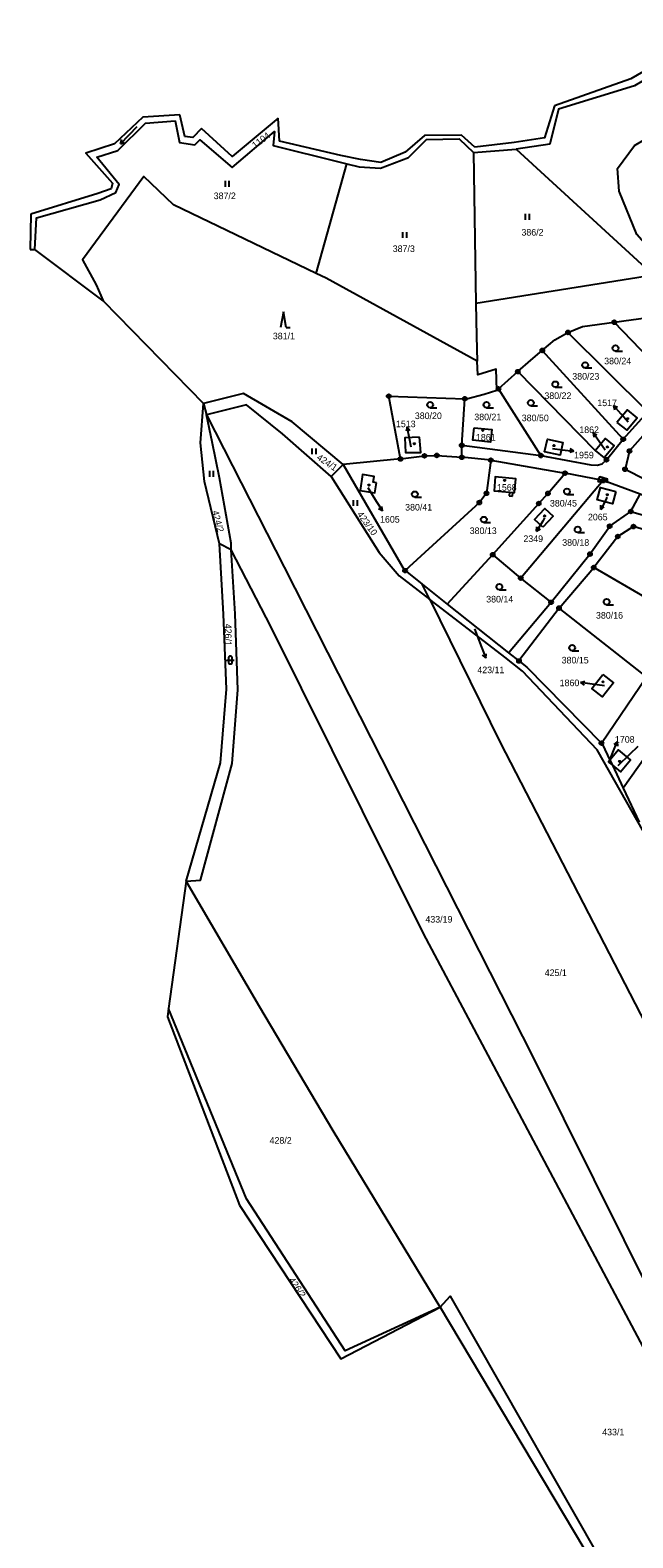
# Model space of a CAD drawing. Extents: x -680203 to -673936, y -1102717 to -1093650.
# Drawn here: x -680070.7 to -679915.5, y -1098200.7 to -1097812.6 of the extents above; entities that cross this region are included whole.
import ezdxf

# ---------------------------------------------------------------- set-up
doc = ezdxf.new("R2010")
doc.units = 0
for name, color, linetype in [('SOxx02xx_Koleje_param další_Popis10', 7, 'Continuous'), ('SOxx02xx_Staničení_Popis10', 7, 'Continuous'), ('SOxxxxxx_Koleje_hlavní_body_Popis10', 7, 'Continuous'), ('SOxxxxxx_Koleje_LN_parametry_Popis10', 7, 'Continuous'), ('SOxxxxxx_Koleje_param další_Popis10', 7, 'Continuous'), ('SOxxxxxx_Osa_bod_P', 7, 'Continuous'), ('SOxxxxxx_Staničení_Popis10', 7, 'Continuous'), ('x_prac', 7, 'Continuous')]:
    doc.layers.add(name, color=color, linetype=linetype)

msp = doc.modelspace()

# ---------------------------------------------------------------- linework, layer by layer
at = {"layer": 'SOxx02xx_Koleje_param další_Popis10'}
for centre, radius in [((-679932.24, -1097890.38), 0.5), ((-679932.24, -1097890.38), 0.0303), ((-679920.32, -1097887.77), 0.5), ((-679920.32, -1097887.77), 0.0303), ((-679938.84, -1097895.02), 0.5), ((-679938.84, -1097895.02), 0.0303), ((-679945.15, -1097900.49), 0.5), ((-679945.15, -1097900.49), 0.0303), ((-679978.36, -1097906.79), 0.5), ((-679950.11, -1097904.92), 0.5), ((-679950.11, -1097904.92), 0.0303), ((-679978.36, -1097906.79), 0.0303), ((-679958.78, -1097907.47), 0.5), ((-679958.78, -1097907.47), 0.0303), ((-679918.02, -1097917.9), 0.5), ((-679918.02, -1097917.9), 0.0303), ((-679969.15, -1097922.15), 0.5), ((-679965.98, -1097922.05), 0.5), ((-679959.58, -1097919.45), 0.5), ((-679959.58, -1097919.45), 0.0303), ((-679939.21, -1097922.09), 0.5), ((-679916.41, -1097920.91), 0.5), ((-679916.41, -1097920.91), 0.0303), ((-679975.33, -1097922.97), 0.5), ((-679975.33, -1097922.97), 0.0303), ((-679969.15, -1097922.15), 0.0303), ((-679965.98, -1097922.05), 0.0303), ((-679959.57, -1097922.54), 0.5), ((-679959.57, -1097922.54), 0.0303), ((-679952.08, -1097923.27), 0.5), ((-679952.08, -1097923.27), 0.0303), ((-679939.21, -1097922.09), 0.0303), ((-679922.32, -1097923.17), 0.5), ((-679922.32, -1097923.17), 0.0303), ((-679917.56, -1097925.62), 0.5), ((-679917.56, -1097925.62), 0.0303), ((-679933, -1097926.62), 0.5), ((-679933, -1097926.62), 0.0303), ((-679923.14, -1097928.54), 0.5), ((-679923.14, -1097928.54), 0.0303), ((-679953.2, -1097931.81), 0.5), ((-679953.2, -1097931.81), 0.0303), ((-679937.39, -1097931.84), 0.5), ((-679937.39, -1097931.84), 0.0303), ((-679955.05, -1097934.19), 0.5), ((-679955.05, -1097934.19), 0.0303), ((-679939.73, -1097934.44), 0.5), ((-679939.73, -1097934.44), 0.0303), ((-679916.06, -1097936.49), 0.5), ((-679916.06, -1097936.49), 0.0303), ((-679921.5, -1097940.27), 0.5), ((-679921.5, -1097940.27), 0.0303), ((-679915.37, -1097940.37), 0.5), ((-679919.41, -1097942.93), 0.5), ((-679919.41, -1097942.93), 0.0303), ((-679951.59, -1097947.6), 0.5), ((-679951.59, -1097947.6), 0.0303), ((-679926.57, -1097947.45), 0.5), ((-679926.57, -1097947.45), 0.0303), ((-679974.15, -1097951.71), 0.5), ((-679974.15, -1097951.71), 0.0303), ((-679925.61, -1097950.92), 0.5), ((-679925.61, -1097950.92), 0.0303), ((-679944.39, -1097953.65), 0.5), ((-679944.39, -1097953.65), 0.0303), ((-679936.59, -1097959.86), 0.5), ((-679936.59, -1097959.86), 0.0303), ((-679934.54, -1097961.35), 0.5), ((-679934.54, -1097961.35), 0.0303), ((-679944.85, -1097974.97), 0.5), ((-679944.85, -1097974.97), 0.0303), ((-679923.62, -1097996.14), 0.5), ((-679923.62, -1097996.14), 0.0303)]:
    msp.add_circle(centre, radius, dxfattribs=at)
at = {"layer": 'SOxx02xx_Staničení_Popis10'}
for p, q in [((-679918.56, -1097911.46), (-679920.53, -1097909.2)), ((-679920.53, -1097909.2), (-679919.49, -1097909.62)), ((-679920.53, -1097909.2), (-679920.25, -1097910.28)), ((-679916.78, -1097913.51), (-679918.56, -1097911.46)), ((-679973.61, -1097914.74), (-679973.91, -1097915.82)), ((-679973.04, -1097917.69), (-679973.61, -1097914.74)), ((-679973.61, -1097914.74), (-679972.93, -1097915.63)), ((-679972.61, -1097919.91), (-679973.04, -1097917.69)), ((-679924.06, -1097918.71), (-679925.78, -1097916.25)), ((-679925.78, -1097916.25), (-679924.8, -1097916.78)), ((-679925.78, -1097916.25), (-679925.62, -1097917.36)), ((-679936.2, -1097920.29), (-679933.69, -1097920.58)), ((-679933.69, -1097920.58), (-679930.71, -1097920.95)), ((-679930.71, -1097920.95), (-679931.77, -1097921.32)), ((-679930.71, -1097920.95), (-679931.64, -1097920.33)), ((-679922.68, -1097920.7), (-679924.06, -1097918.71)), ((-679983.72, -1097930.34), (-679981.6, -1097933.8)), ((-679922.45, -1097933.3), (-679923.81, -1097935.97)), ((-679922.2, -1097932.81), (-679922.45, -1097933.3)), ((-679981.6, -1097933.8), (-679980.01, -1097936.34)), ((-679980.01, -1097936.34), (-679980.96, -1097935.76)), ((-679980.01, -1097936.34), (-679980.12, -1097935.23)), ((-679923.81, -1097935.97), (-679923.8, -1097934.85)), ((-679923.81, -1097935.97), (-679922.91, -1097935.31)), ((-679938.75, -1097939), (-679940.3, -1097941.57)), ((-679940.3, -1097941.57), (-679940.21, -1097940.46)), ((-679940.3, -1097941.57), (-679939.35, -1097940.97)), ((-679938.25, -1097938.16), (-679938.75, -1097939)), ((-679956.32, -1097966.73), (-679954.48, -1097971.42)), ((-679954.48, -1097971.42), (-679953.41, -1097974.22)), ((-679953.41, -1097974.22), (-679954.23, -1097973.47)), ((-679953.41, -1097974.22), (-679953.3, -1097973.11)), ((-679928.99, -1097980.55), (-679927.93, -1097980.2)), ((-679926.02, -1097980.97), (-679928.99, -1097980.55)), ((-679928.99, -1097980.55), (-679928.07, -1097981.19)), ((-679922.85, -1097981.41), (-679926.02, -1097980.97)), ((-679921.62, -1098000.91), (-679920.68, -1097998.54)), ((-679920.68, -1097998.54), (-679919.56, -1097995.76)), ((-679919.56, -1097995.76), (-679920.4, -1097996.5)), ((-679919.56, -1097995.76), (-679919.47, -1097996.87)), ((-679919.28, -1098001.87), (-679916.3, -1097998.95)), ((-679916.3, -1097998.95), (-679914.14, -1097996.86))]:
    msp.add_line(p, q, dxfattribs=at)
at = {"layer": 'SOxxxxxx_Koleje_hlavní_body_Popis10'}
for p, q in [((-680043.2, -1097837.5), (-680047.37, -1097841.81)), ((-680047.37, -1097841.81), (-680047.05, -1097840.76)), ((-680047.37, -1097841.81), (-680046.33, -1097841.46)), ((-680020.4, -1097852.9), (-680020.4, -1097851.4)), ((-680019.4, -1097852.9), (-680019.4, -1097851.4)), ((-679943.15, -1097861.39), (-679943.15, -1097859.89)), ((-679942.15, -1097861.39), (-679942.15, -1097859.89)), ((-679974.75, -1097866.06), (-679974.75, -1097864.56)), ((-679973.75, -1097866.06), (-679973.75, -1097864.56)), ((-680005.49, -1097885.12), (-680006.24, -1097889.12)), ((-680004.74, -1097889.12), (-680005.49, -1097885.12)), ((-680004.74, -1097889.12), (-680003.74, -1097889.12)), ((-679919.99, -1097895.2), (-679918.24, -1097895.2)), ((-679927.82, -1097899.54), (-679926.07, -1097899.54)), ((-679935.5, -1097904.48), (-679933.75, -1097904.48)), ((-679967.72, -1097909.78), (-679965.97, -1097909.78)), ((-679953.19, -1097909.78), (-679951.44, -1097909.78)), ((-679941.81, -1097909.28), (-679940.06, -1097909.28)), ((-679998.06, -1097921.76), (-679998.06, -1097920.26)), ((-679997.06, -1097921.76), (-679997.06, -1097920.26)), ((-680024.44, -1097927.55), (-680024.44, -1097926.05)), ((-680023.44, -1097927.55), (-680023.44, -1097926.05)), ((-679987.43, -1097935.04), (-679987.43, -1097933.54)), ((-679986.43, -1097935.04), (-679986.43, -1097933.54)), ((-679971.65, -1097932.81), (-679969.9, -1097932.81)), ((-679932.5, -1097932.07), (-679930.75, -1097932.07)), ((-679953.9, -1097939.33), (-679952.15, -1097939.33)), ((-679929.74, -1097941.89), (-679927.99, -1097941.89)), ((-679949.9, -1097956.63), (-679948.15, -1097956.63)), ((-679922.28, -1097960.5), (-679920.53, -1097960.5)), ((-679931.15, -1097972.34), (-679929.4, -1097972.34)), ((-680020.13, -1097974.73), (-680018.13, -1097974.73)), ((-680019.63, -1097974.23), (-680019.63, -1097975.23)), ((-680018.63, -1097975.23), (-680018.63, -1097974.23))]:
    msp.add_line(p, q, dxfattribs=at)
for centre in [(-679919.99, -1097894.45), (-679927.82, -1097898.79), (-679935.5, -1097903.73), (-679967.72, -1097909.03), (-679953.19, -1097909.03), (-679941.81, -1097908.53), (-679971.65, -1097932.06), (-679932.5, -1097931.32), (-679953.9, -1097938.58), (-679929.74, -1097941.14), (-679949.9, -1097955.88), (-679922.28, -1097959.75), (-679931.15, -1097971.59)]:
    msp.add_circle(centre, 0.75, dxfattribs=at)
for centre, start, end in [((-680019.13, -1097974.23), 0, 180), ((-680019.13, -1097975.23), 180, 359.9879)]:
    msp.add_arc(centre, 0.5, start, end, dxfattribs=at)
at = {"layer": 'SOxxxxxx_Koleje_LN_parametry_Popis10'}
for points in [[(-679924.53, -1097928.79), (-679923.95, -1097928.88), (-679923.79, -1097928.41), (-679924.45, -1097928.29)], [(-679924.45, -1097928.29), (-679923.79, -1097928.41), (-679923.74, -1097928.27), (-679922.67, -1097928.57), (-679922.68, -1097928.71), (-679922.08, -1097928.93), (-679922.07, -1097928.13), (-679924.06, -1097927.55)]]:
    msp.add_lwpolyline(points, close=True, dxfattribs=at)
at = {"layer": 'SOxxxxxx_Koleje_param další_Popis10'}
for centre in [(-679916.86, -1097912.62), (-679954.15, -1097915.61), (-679971.78, -1097919.05), (-679935.84, -1097919.52), (-679922.1, -1097919.85), (-679983.47, -1097929.7), (-679948.53, -1097928.5), (-679922.13, -1097932.17), (-679938.26, -1097937.63), (-679923.22, -1097980.34), (-679921.35, -1098001.12), (-679918.95, -1098000.82)]:
    msp.add_circle(centre, 0.175, dxfattribs=at)
at = {"layer": 'SOxxxxxx_Staničení_Popis10'}
msp.add_line((-679947.26, -1097931.51), (-679946.44, -1097931.59), dxfattribs=at)
at = {"layer": 'x_prac'}
for p, q in [((-680032.12, -1097834.34), (-680041.62, -1097834.93)), ((-680006.46, -1097841.12), (-680006.86, -1097835.19)), ((-679959.68, -1097839.57), (-679969.2, -1097839.65)), ((-679956.25, -1097842.69), (-679959.68, -1097839.57)), ((-679956.59, -1097844.07), (-679945.55, -1097843.21)), ((-679956.59, -1097844.07), (-679955.91, -1097882.92)), ((-679945.55, -1097843.21), (-679910.23, -1097875.63)), ((-679997.01, -1097875.2), (-679989.15, -1097846.99)), ((-680053.24, -1097854.63), (-680070.47, -1097859.92)), ((-680070.47, -1097859.92), (-680070.65, -1097869)), ((-680070.65, -1097869), (-680069.42, -1097869.02)), ((-680051.84, -1097882.27), (-680069.42, -1097869.02)), ((-679994.49, -1097876.41), (-679997.01, -1097875.2)), ((-680053.69, -1097878.16), (-680051.84, -1097882.27)), ((-679955.65, -1097897.8), (-679994.49, -1097876.41)), ((-679910.23, -1097875.63), (-679955.91, -1097882.92)), ((-680051.84, -1097882.27), (-680026, -1097908.7)), ((-679955.91, -1097882.92), (-679955.76, -1097891.32)), ((-679911.68, -1097910.84), (-679932.24, -1097890.38)), ((-679905.14, -1097903.62), (-679920.32, -1097887.77)), ((-679955.76, -1097891.32), (-679955.65, -1097897.8)), ((-679918.02, -1097917.9), (-679938.84, -1097895.02)), ((-679950.11, -1097904.92), (-679945.15, -1097900.49)), ((-679945.15, -1097900.49), (-679925.2, -1097920.79)), ((-679950.51, -1097905.28), (-679950.11, -1097904.92)), ((-679939.21, -1097922.09), (-679950.11, -1097904.92)), ((-680026, -1097908.7), (-680025.27, -1097911.61)), ((-679959.58, -1097919.45), (-679958.78, -1097907.47)), ((-679918.02, -1097917.9), (-679911.68, -1097910.84)), ((-679922.32, -1097923.17), (-679918.02, -1097917.9)), ((-679959.57, -1097922.54), (-679959.58, -1097919.45)), ((-679959.58, -1097919.45), (-679939.21, -1097922.09)), ((-679925.2, -1097920.79), (-679922.89, -1097922.65)), ((-679993.21, -1097927.47), (-679990.1, -1097924.39)), ((-679975.33, -1097922.97), (-679990.1, -1097924.39)), ((-679952.08, -1097923.27), (-679959.57, -1097922.54)), ((-679952.08, -1097923.27), (-679933, -1097926.62)), ((-679922.89, -1097922.65), (-679922.32, -1097923.17)), ((-680021.96, -1097944.82), (-680025.77, -1097928.73)), ((-679923.14, -1097928.54), (-679944.39, -1097953.65)), ((-679923.14, -1097928.54), (-679933, -1097926.62)), ((-679913.64, -1097932.02), (-679923.14, -1097928.54)), ((-679947.34, -1097932.44), (-679946.52, -1097932.51)), ((-679916.06, -1097936.49), (-679913.64, -1097932.02)), ((-680020.91, -1097962.93), (-680021.96, -1097944.82)), ((-680018.89, -1097946.34), (-680021.96, -1097944.82)), ((-680018.89, -1097946.34), (-680018.96, -1097944.64)), ((-680017.91, -1097962.81), (-680018.89, -1097946.34)), ((-679963.31, -1097960.31), (-679951.59, -1097947.6)), ((-679944.39, -1097953.65), (-679951.59, -1097947.6)), ((-679974.15, -1097951.71), (-679969.77, -1097955.18)), ((-679934.54, -1097961.35), (-679925.61, -1097950.92)), ((-679901.33, -1097965.01), (-679925.61, -1097950.92)), ((-679975.64, -1097953.08), (-679967.83, -1097959.12)), ((-679969.77, -1097955.18), (-679963.31, -1097960.31)), ((-679967.83, -1097959.12), (-679969.77, -1097955.18)), ((-679936.59, -1097959.86), (-679944.39, -1097953.65)), ((-679963.31, -1097960.31), (-679947.52, -1097972.84)), ((-679947.52, -1097972.84), (-679936.59, -1097959.86)), ((-679934.54, -1097961.35), (-679944.85, -1097974.97)), ((-679912.02, -1097979.05), (-679934.54, -1097961.35)), ((-679947.52, -1097972.84), (-679944.85, -1097974.97)), ((-679923.62, -1097996.14), (-679912.02, -1097979.05)), ((-679901.27, -1097983.98), (-679918.05, -1098007.7)), ((-680030.49, -1098031.65), (-680021.65, -1098001.16)), ((-679921.43, -1098000.47), (-679920.8, -1098001.82)), ((-679920.8, -1098001.82), (-679918.05, -1098007.7)), ((-679918.05, -1098007.7), (-679913.92, -1098016.51)), ((-680030.49, -1098031.65), (-680035.04, -1098064.4)), ((-680035.04, -1098064.4), (-680035.34, -1098066.58)), ((-680014.99, -1098113.45), (-680035.04, -1098064.4))]:
    msp.add_line(p, q, dxfattribs=at)
for points in [[(-679894.47, -1097812.57), (-679916.06, -1097825.13), (-679935.71, -1097832.08)], [(-679905.81, -1097821.39), (-679915.09, -1097826.89), (-679934.68, -1097832.95), (-679936.92, -1097841.89), (-679945.55, -1097843.21)], [(-679905.39, -1097874.69), (-679910.72, -1097869.5), (-679914.54, -1097865.19), (-679919.02, -1097854.02), (-679919.51, -1097848.2), (-679915.14, -1097842.24), (-679910.49, -1097839.56), (-679899.01, -1097837.6), (-679890.96, -1097834.49), (-679881.95, -1097827.47), (-679874.33, -1097827.56), (-679868.96, -1097846.47), (-679865.52, -1097860.62)], [(-679935.71, -1097832.08), (-679938.26, -1097840.26), (-679946.05, -1097841.52), (-679956.25, -1097842.69)], [(-680069.42, -1097869.02), (-680068.99, -1097860.87), (-680052.65, -1097856.27), (-680048.64, -1097854.4), (-680047.76, -1097852.3), (-680053.5, -1097845.3), (-680048.09, -1097843.52), (-680040.97, -1097836.52), (-680033.32, -1097835.94), (-680032.18, -1097841.48), (-680028.27, -1097842.06), (-680026.99, -1097840.82), (-680018.66, -1097847.9), (-680007.73, -1097838.63), (-680008.08, -1097842.26), (-679991.22, -1097846.5), (-679989.15, -1097846.99)], [(-680041.62, -1097834.93), (-680048.92, -1097841.87), (-680056.31, -1097844.27), (-680049.48, -1097851.98), (-680049.8, -1097853.43), (-680053.24, -1097854.63)], [(-680026.58, -1097837.92), (-680028.82, -1097840.21), (-680030.84, -1097839.99), (-680032.12, -1097834.34)], [(-680006.86, -1097835.19), (-680018.67, -1097845.08), (-680026.58, -1097837.92)], [(-679969.2, -1097839.65), (-679974.14, -1097844.02), (-679980.36, -1097846.62)], [(-679980.36, -1097846.62), (-679985.6, -1097845.9), (-679990.67, -1097844.88), (-680006.46, -1097841.12)], [(-679989.15, -1097846.99), (-679985.98, -1097847.74), (-679980.46, -1097848.12), (-679973.32, -1097845.32), (-679968.61, -1097840.73), (-679960.2, -1097840.52), (-679956.59, -1097844.07)], [(-679997.01, -1097875.2), (-680033.8, -1097857.51), (-680041.36, -1097850.22), (-680057.22, -1097871.74), (-680053.69, -1097878.16)], [(-679920.32, -1097887.77), (-679904.73, -1097885.63), (-679892.06, -1097885.34)], [(-679938.84, -1097895.02), (-679935.63, -1097892.33), (-679932.24, -1097890.38)], [(-679932.24, -1097890.38), (-679928.49, -1097888.9), (-679920.32, -1097887.77)], [(-679950.51, -1097905.28), (-679950.71, -1097899.88), (-679955.41, -1097901.34), (-679955.65, -1097897.8)], [(-679945.15, -1097900.49), (-679941.79, -1097897.49), (-679938.84, -1097895.02)], [(-679990.1, -1097924.39), (-680003.18, -1097913.43), (-680015.73, -1097906.13), (-680026, -1097908.7)], [(-679958.78, -1097907.47), (-679958.33, -1097907.49), (-679953.84, -1097906.26), (-679950.51, -1097905.28)], [(-680025.77, -1097928.73), (-680026.8, -1097918.84), (-680026, -1097908.7)], [(-679993.21, -1097927.47), (-680005.75, -1097916.5), (-680015, -1097909.04), (-680025.27, -1097911.61)], [(-679975.33, -1097922.97), (-679978.36, -1097906.79), (-679958.78, -1097907.47)], [(-679919.62, -1097913.6), (-679917.12, -1097915.54), (-679914.46, -1097912.38), (-679916.88, -1097910.34), (-679919.62, -1097913.6)], [(-679905.45, -1097908.48), (-679916.41, -1097920.91), (-679917.56, -1097925.62), (-679901.97, -1097933.51)], [(-680018.96, -1097944.64), (-680021.88, -1097927.8), (-680023.82, -1097918.53), (-680025.27, -1097911.61)], [(-680025.27, -1097911.61), (-680005.28, -1097950.81), (-679941.2, -1098077.06), (-679902.29, -1098155.38), (-679878.56, -1098204.95)], [(-679970.44, -1097917.33), (-679974.25, -1097917.55), (-679974.03, -1097921.32), (-679970.1, -1097921.34), (-679970.44, -1097917.33)], [(-679956.42, -1097914.91), (-679951.82, -1097915.38), (-679952.16, -1097918.61), (-679956.76, -1097918.14), (-679956.42, -1097914.91)], [(-679938.27, -1097921.13), (-679937.49, -1097917.83), (-679933.53, -1097918.72), (-679934.25, -1097922.01), (-679938.27, -1097921.13)], [(-679925.2, -1097920.79), (-679922.65, -1097917.68), (-679920.35, -1097919.6), (-679922.89, -1097922.65)], [(-679990.1, -1097924.39), (-679974.42, -1097951.5), (-679974.15, -1097951.71)], [(-679975.33, -1097922.97), (-679969.15, -1097922.15), (-679965.98, -1097922.05), (-679959.57, -1097922.54)], [(-679952.08, -1097923.27), (-679953.2, -1097931.81), (-679955.05, -1097934.19), (-679974.15, -1097951.71)], [(-679939.21, -1097922.09), (-679926.33, -1097924.49), (-679924.7, -1097924.6), (-679923.43, -1097924.19), (-679922.32, -1097923.17)], [(-679993.21, -1097927.47), (-679980.87, -1097947.08), (-679975.64, -1097953.08)], [(-679981.53, -1097929.09), (-679982.37, -1097928.97), (-679982.15, -1097927.48), (-679985.12, -1097926.94), (-679985.75, -1097931.12), (-679981.92, -1097931.69), (-679981.53, -1097929.09)], [(-679951.59, -1097947.6), (-679939.73, -1097934.44), (-679937.39, -1097931.84), (-679933, -1097926.62)], [(-679946.52, -1097932.51), (-679946.44, -1097931.59), (-679946.02, -1097931.63), (-679945.67, -1097928.04), (-679950.96, -1097927.6), (-679951.27, -1097931.17), (-679947.26, -1097931.51), (-679947.34, -1097932.44)], [(-679919.92, -1097931.36), (-679920.75, -1097934.55), (-679924.69, -1097933.49), (-679923.88, -1097930.32), (-679919.92, -1097931.36)], [(-679916.06, -1097936.49), (-679898.34, -1097941.64), (-679899.31, -1097938.64), (-679913.64, -1097932.02)], [(-679938.7, -1097940.53), (-679940.83, -1097938.57), (-679938.2, -1097935.72), (-679936.08, -1097937.67), (-679938.7, -1097940.53)], [(-679936.59, -1097959.86), (-679926.57, -1097947.45), (-679921.5, -1097940.27), (-679916.06, -1097936.49)], [(-679889.33, -1097949.28), (-679899.7, -1097945.12), (-679915.37, -1097940.37), (-679919.41, -1097942.93), (-679925.61, -1097950.92)], [(-679885.5, -1098206.93), (-679911.39, -1098154.28), (-679969.42, -1098045.11), (-680008.66, -1097966.29), (-680018.89, -1097946.34)], [(-679912.75, -1098019.03), (-679924.75, -1097997.83), (-679943.92, -1097977.59), (-679948.52, -1097974.03), (-679964.54, -1097961.66), (-679967.83, -1097959.12)], [(-679967.83, -1097959.12), (-679949.65, -1097995.96), (-679905.6, -1098081.35), (-679856.1, -1098196.93)], [(-680030.49, -1098031.65), (-680026.84, -1098031.36), (-680018.66, -1098001.39), (-680017.17, -1097982.43), (-680017.91, -1097962.81)], [(-680021.65, -1098001.16), (-680020.16, -1097982.2), (-680020.91, -1097962.93)], [(-679944.85, -1097974.97), (-679942.84, -1097976.56), (-679923.62, -1097996.14)], [(-679923.28, -1097978.43), (-679920.54, -1097980.58), (-679923.36, -1097984.18), (-679926.11, -1097982.02), (-679923.28, -1097978.43)], [(-679923.62, -1097996.14), (-679923.31, -1097996.46), (-679921.43, -1098000.47)], [(-679920.8, -1098001.82), (-679918.76, -1098003.52), (-679916.13, -1098000.43), (-679919.21, -1097997.83), (-679921.43, -1098000.47)], [(-679921.43, -1098000.47), (-679921.84, -1098000.95), (-679920.8, -1098001.82)], [(-679965.16, -1098141.3), (-679992.66, -1098095.95), (-680011.53, -1098064.1), (-680030.49, -1098031.65)], [(-680035.34, -1098066.58), (-680016.8, -1098115.08), (-679990.67, -1098154.6), (-679965.16, -1098141.3)], [(-679965.16, -1098141.3), (-679989.55, -1098152.55), (-680014.99, -1098113.45)], [(-679965.16, -1098141.3), (-679962.53, -1098138.49), (-679918.07, -1098216.55), (-679916.32, -1098283.78)], [(-679965.16, -1098141.3), (-679920.17, -1098216.79), (-679922.35, -1098282.77)]]:
    msp.add_lwpolyline(points, dxfattribs=at)

# ---------------------------------------------------------------- texts
at = {"layer": 'SOxxxxxx_Osa_bod_P'}
for s, rotation, p in [('1104', 37, (-680012.75, -1097843.11)), ('424/1', 326, (-679997.05, -1097922.96)), ('424/2', 285, (-680023.85, -1097936.48)), ('423/10', 306, (-679986.62, -1097937.23)), ('426/1', 270, (-680020.53, -1097965.39)), ('426/2', 304, (-680004.18, -1098134.35))]:
    msp.add_text(s, height=1.7, rotation=rotation, dxfattribs=at).set_placement(p)
for s, p in [('387/2', (-680023.41, -1097856.07)), ('386/2', (-679944.21, -1097865.46)), ('387/3', (-679977.34, -1097869.69)), ('381/1', (-680008.19, -1097892.17)), ('380/24', (-679922.92, -1097898.59)), ('380/23', (-679931.13, -1097902.54)), ('380/22', (-679938.31, -1097907.53)), ('1517', (-679924.69, -1097909.36)), ('1513', (-679976.51, -1097914.79)), ('380/20', (-679971.65, -1097912.7)), ('380/21', (-679956.35, -1097912.99)), ('380/50', (-679944.13, -1097913.25)), ('1861', (-679955.92, -1097918.24)), ('1862', (-679929.32, -1097916.3)), ('1959', (-679930.65, -1097922.82)), ('1568', (-679950.51, -1097931.15)), ('380/45', (-679936.88, -1097935.21)), ('380/41', (-679974.14, -1097936.24)), ('2065', (-679927.1, -1097938.77)), ('1605', (-679980.6, -1097939.36)), ('380/13', (-679957.53, -1097942.3)), ('2349', (-679943.71, -1097944.34)), ('380/18', (-679933.72, -1097945.32)), ('380/14', (-679953.28, -1097959.91)), ('380/16', (-679925.03, -1097964.07)), ('423/11', (-679955.56, -1097978.11)), ('380/15', (-679933.86, -1097975.61)), ('1860', (-679934.38, -1097981.46)), ('1708', (-679920.15, -1097996.01)), ('433/19', (-679968.93, -1098042.32)), ('425/1', (-679938.22, -1098056.08)), ('428/2', (-680009.03, -1098099.25)), ('433/1', (-679923.43, -1098174.34))]:
    msp.add_text(s, height=1.7, dxfattribs=at).set_placement(p)

doc.saveas('drawing.dxf')
